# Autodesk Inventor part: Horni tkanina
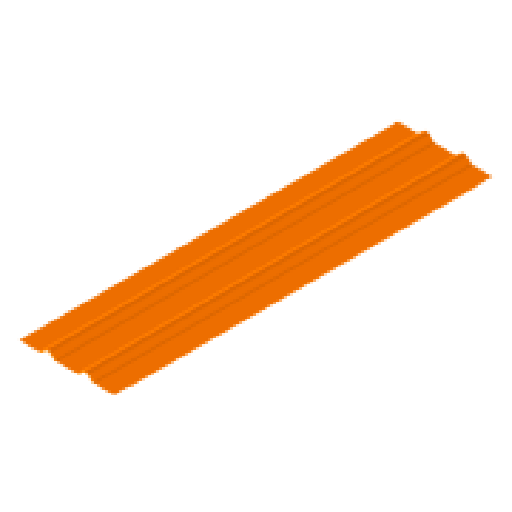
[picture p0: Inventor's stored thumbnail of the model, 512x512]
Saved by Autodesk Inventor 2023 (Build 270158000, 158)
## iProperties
Created: 2025-03
Part Number: Horni tkanina
Material: Všeobecné
Document SubType Name: Modeling
Designer: tomik
Density: 1 g/cm^3
Appearance: Výchozí(1)
Author: tomik
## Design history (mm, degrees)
sketch "Náčrt1"
  geometry: L1 (0, 0)-(0, 10.449); L2 (0, 0)-(6.785, 0); L3 (0, 0)-(0, 4); L4 (0, 0)-(4, 0); L5 (3.268, 0.732)-(0, 4); L6 (0, 0)-(-6.785, 0); L7 (0, 0)-(-4, 0); L8 (-3.268, 0.732)-(0, 4); A1 r 2.5 centre (5.036, 2.5) between (3.268, 0.732) and (5.036, 0); A2 r 2.5 centre (-5.036, 2.5) between (-5.036, 0) and (-3.268, 0.732)
  constraints: 16 end point, 5 point on line, 5 symmetric about line, 4 point on circle, 2 centre point, 2 tangent, 1 horizontal, 1 vertical, 1 other
  dimensions: "d0" = 4 distance of L1.start L3.end; "d3" = 4 distance of L1.start L4.end; "d4" = 5 diameter of A1; "d5" = 5.03553 distance from line of A1.end L1
extrude "Vysunutí1" new body sketch "Náčrt1" distance "d6" = 200; taper "d7" = 0 deg
fillet "Zaoblení1" dims "d8" = 2
feature "Zesílit1" dims "d9" = 0.6, "d10" = 2
sketch "Náčrt2"
  geometry: 1 further point
node "Pracovní rovina1"
node "Pracovní rovina2"
mirror "Zrcadlit2"
sketch "Náčrt4"
  geometry: L1 (0, 0)-(0, 200) reference; L2 (0, 0)-(0.6, 0) reference; L3 (0.6, 0)-(0.6, 200) reference; L4 (0, 200)-(0.6, 200) reference; 1 further point
extrude "Vysunutí3" join sketch "Náčrt4" stored distance "d15" = 10; taper "d16" = 0 deg
mirror "Zrcadlit3"
node "Pracovní rovina3"
sketch "Náčrt6"
  geometry: L1 (0, 0)-(0, 200) reference; L2 (0, 200)-(0.6, 200) reference; L3 (0.6, 0)-(0.6, 200) reference; L4 (0, 0)-(0.6, 0) reference; 1 further point
extrude "Vysunutí4" join sketch "Náčrt6" stored distance "d18" = 10; taper "d19" = 0 deg
mirror "Zrcadlit4"
node "Pracovní rovina4"
sketch "Náčrt8"
  geometry: L1 (-20.036, 0)-(-10.071, 0) reference; L2 (29.964, 0)-(29.964, 200) reference; L3 (-20.036, 0)-(29.964, 0); L4 (29.964, 0)-(29.964, 8); L5 (29.964, 8)-(-20.036, 8); L6 (-20.036, 8)-(-20.036, 0); 3 further points
  constraints: 8 end point, 2 parallel, 1 horizontal, 1 perpendicular, 1 point on line
  dimensions: "d33" = 8 distance between parallel lines of L3 L5
extrude "Vysunutí6" cut sketch "Náčrt8" distance "d34" = 0.5; taper "d35" = 0 deg
fillet "Zaoblení5" dims "d36" = 0.8
chamfer "Zkosení2" distance "d37" = 0.4999; stored, may be unused: second distance "d38" = 2, angle "d39" = 45 deg
mirror "Zrcadlit6"
node "Těleso1"
node "Těleso3"
node "Promítnutá smyčka2"
node "Promítnutá smyčka4"
other parameters: "d11" = 25, "d17" = -25
